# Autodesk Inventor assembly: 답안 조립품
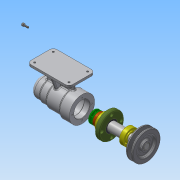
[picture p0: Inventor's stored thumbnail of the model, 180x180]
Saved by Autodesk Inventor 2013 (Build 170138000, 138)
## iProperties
Created: 2016-06
Part Number: 답안 조립품
Document SubType Name: Assembly
Designer: Administrator
Author: Administrator
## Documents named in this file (12)
- C:\Users\Administrator\Desktop\460608V1002\답안 조립품.iam
- C:\Users\Administrator\Desktop\460608V1002\본체.ipt
- C:\Users\Administrator\Desktop\460608V1002\V벨트풀리.ipt
- C:\Users\Administrator\Desktop\460608V1002\멈춤나사 M3x8.ipt
- C:\Users\Administrator\Desktop\460608V1002\베어링 6004.ipt
- C:\Users\Administrator\Desktop\460608V1002\베어링 51202.ipt
- C:\Users\Administrator\Desktop\460608V1002\볼트 M4 x 12.ipt
- C:\Users\Administrator\Desktop\460608V1002\어댑터슬리브.ipt
- C:\Users\Administrator\Desktop\460608V1002\오일 실.ipt
- C:\Users\Administrator\Desktop\460608V1002\축.ipt
- C:\Users\Administrator\Desktop\460608V1002\커버.ipt
- C:\Users\Administrator\Desktop\460608V1002\키 5 x 5 x 16.ipt
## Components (2 placed, 2 different names)
1. V벨트풀리:1 — 플러쉬:1
2. ISO 4762 M4 x 12:1
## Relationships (1: Flush 1)
- 플러쉬:1 [Flush]: V벨트풀리:1
